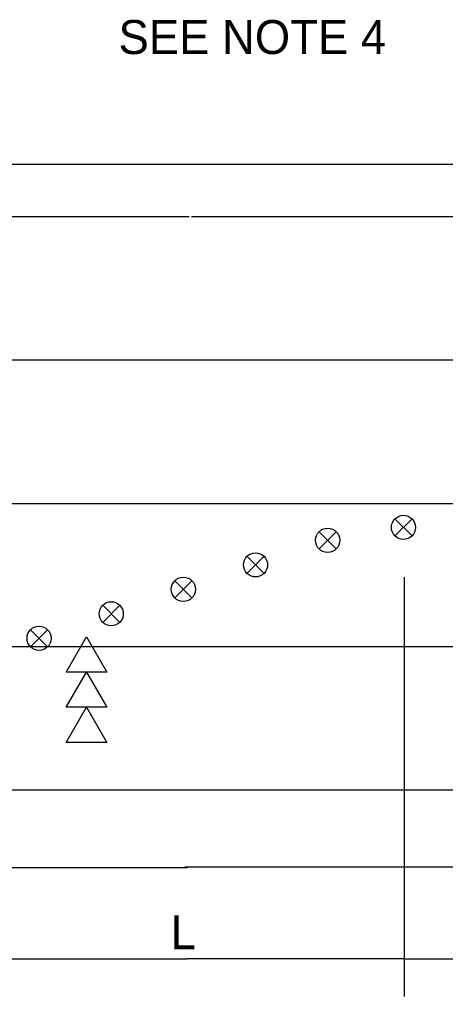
# Model space of a CAD drawing. Extents: x 99988 to 100172, y 99995 to 100047.
# Drawn here: x 100008.675 to 100009.804, y 100004.173 to 100006.76 of the extents above; entities that cross this region are included whole.
import ezdxf

# ---------------------------------------------------------------- set-up
doc = ezdxf.new("R2010")
doc.units = 0
for name, color, linetype in [('Default', 7, 'Continuous'), ('Level 15', 7, 'Continuous'), ('Level 20', 7, 'Continuous'), ('TR_WZ_SequentialArrowTypeC', 7, 'Continuous'), ('TR_WZ_WorkZoneDetails', 7, 'Continuous')]:
    doc.layers.add(name, color=color, linetype=linetype)

msp = doc.modelspace()

# ---------------------------------------------------------------- linework, layer by layer
at = {"layer": 'Default'}
for p, q in [((100002.5342, 100005.8585), (100011.4419, 100005.8585)), ((100002.5316, 100005.4785), (100014.1914, 100005.4785)), ((100009.7155, 100005.4376), (100009.6702, 100005.3924)), ((100009.6702, 100005.4376), (100009.7155, 100005.3924)), ((100009.5146, 100005.4034), (100009.4694, 100005.3581)), ((100009.4694, 100005.4034), (100009.5146, 100005.3581)), ((100009.3235, 100005.3386), (100009.2782, 100005.2933)), ((100009.2782, 100005.3386), (100009.3235, 100005.2933)), ((100009.1323, 100005.2737), (100009.087, 100005.2285)), ((100009.087, 100005.2737), (100009.1323, 100005.2285)), ((100008.9411, 100005.2089), (100008.8958, 100005.1636)), ((100008.8958, 100005.2089), (100008.9411, 100005.1636)), ((100008.7499, 100005.144), (100008.7046, 100005.0988)), ((100008.7046, 100005.144), (100008.7499, 100005.0988)), ((100002.5342, 100005.0998), (100011.6853, 100005.0998))]:
    msp.add_line(p, q, dxfattribs=at)
for centre in [(100009.6929, 100005.415), (100009.492, 100005.3808), (100009.3008, 100005.3159), (100009.1096, 100005.2511), (100008.9185, 100005.1863), (100008.7273, 100005.1214)]:
    msp.add_circle(centre, 0.032, dxfattribs=at)
at = {"layer": 'Level 15'}
for p, q in [((100008.5444, 100004.2732), (100009.1194, 100004.2732)), ((100009.6944, 100004.2732), (100009.1194, 100004.2732)), ((100009.6944, 100004.2732), (100010.2785, 100004.2732))]:
    msp.add_line(p, q, dxfattribs=at)
at = {"layer": 'TR_WZ_SequentialArrowTypeC'}
msp.add_lwpolyline([(100008.9071, 100004.8456), (100008.7991, 100004.8456), (100008.8531, 100004.9389), (100008.7991, 100004.9389), (100008.8531, 100005.0322), (100008.7991, 100005.0322), (100008.8531, 100005.1255), (100008.9071, 100005.0322), (100008.8531, 100005.0322), (100008.9071, 100004.9389), (100008.8531, 100004.9389)], close=True, dxfattribs=at)
at = {"layer": 'TR_WZ_WorkZoneDetails'}
for p, q in [((100002.5342, 100006.3767), (100014.2093, 100006.3767)), ((100002.5342, 100006.2379), (100009.125, 100006.2379)), ((100009.1315, 100006.2379), (100014.2061, 100006.2379)), ((100009.6944, 100005.283), (100009.6944, 100004.1732)), ((100006.9431, 100004.7201), (100009.1923, 100004.7201)), ((100009.1206, 100004.7201), (100013.3383, 100004.7201)), ((100005.4304, 100004.5142), (100009.1205, 100004.5142)), ((100009.1133, 100004.5164), (100014.2093, 100004.5164))]:
    msp.add_line(p, q, dxfattribs=at)

# ---------------------------------------------------------------- texts
at = {"layer": 'Level 20'}
msp.add_text('SEE NOTE 4', height=0.09, rotation=360, dxfattribs=at).set_placement((100008.9378, 100006.6683))
msp.add_text('L', height=0.09, dxfattribs=at).set_placement((100009.0761, 100004.2982))

doc.saveas('drawing.dxf')
